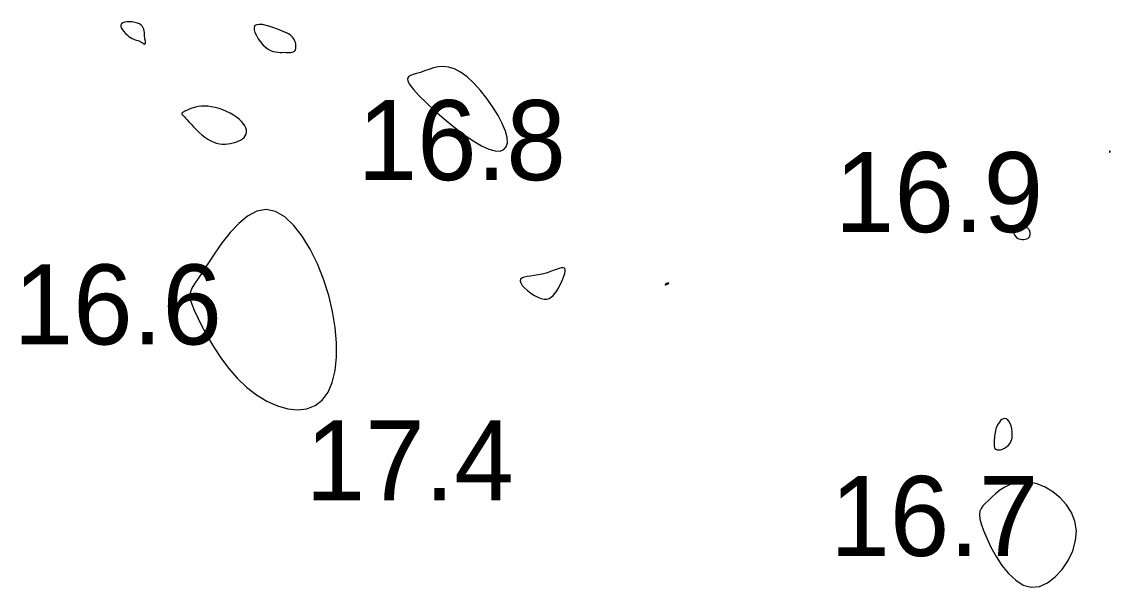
# Model space of a CAD drawing. Extents: x 3040093 to 3056816, y 408076 to 509144.
# Drawn here: x 3045420.5 to 3045488.5, y 433988.6 to 434023.9 of the extents above; entities that cross this region are included whole.
import ezdxf

# ---------------------------------------------------------------- set-up
doc = ezdxf.new("R2010")
doc.units = 0
doc.layers.add('V-CHAN-CONT-EL17', color=7, linetype='Continuous')
doc.layers.add('V-TOPO-SOUN-0610', color=7, linetype='Continuous')

msp = doc.modelspace()

# ---------------------------------------------------------------- linework, layer by layer
at = {"layer": 'V-CHAN-CONT-EL17'}
for points in [[(3045427.309, 434022.925), (3045427.41, 434022.867), (3045427.506, 434022.821), (3045427.596, 434022.784), (3045427.679, 434022.755), (3045427.755, 434022.73), (3045427.824, 434022.708), (3045427.884, 434022.686), (3045427.936, 434022.663), (3045427.981, 434022.638), (3045428.019, 434022.614), (3045428.051, 434022.59), (3045428.079, 434022.568), (3045428.104, 434022.549), (3045428.126, 434022.533), (3045428.146, 434022.522), (3045428.166, 434022.517), (3045428.184, 434022.516), (3045428.201, 434022.521), (3045428.216, 434022.532), (3045428.228, 434022.547), (3045428.238, 434022.567), (3045428.243, 434022.591), (3045428.245, 434022.621), (3045428.242, 434022.654), (3045428.236, 434022.693), (3045428.227, 434022.738), (3045428.217, 434022.788), (3045428.206, 434022.845), (3045428.195, 434022.909), (3045428.186, 434022.98), (3045428.18, 434023.06), (3045428.176, 434023.148), (3045428.171, 434023.242), (3045428.161, 434023.339), (3045428.141, 434023.436), (3045428.107, 434023.531), (3045428.054, 434023.62), (3045427.978, 434023.701), (3045427.874, 434023.771), (3045427.74, 434023.828), (3045427.584, 434023.87), (3045427.416, 434023.897), (3045427.245, 434023.908), (3045427.082, 434023.903), (3045426.936, 434023.88), (3045426.817, 434023.839), (3045426.735, 434023.78), (3045426.697, 434023.703), (3045426.699, 434023.611), (3045426.735, 434023.509), (3045426.799, 434023.4), (3045426.884, 434023.29), (3045426.984, 434023.184), (3045427.092, 434023.085), (3045427.202, 434022.997)], [(3045435.901, 434022.2), (3045436.059, 434022.115), (3045436.213, 434022.058), (3045436.363, 434022.023), (3045436.509, 434022.004), (3045436.648, 434021.997), (3045436.782, 434021.997), (3045436.908, 434021.999), (3045437.026, 434021.997), (3045437.136, 434021.995), (3045437.237, 434021.994), (3045437.328, 434021.997), (3045437.409, 434022.006), (3045437.478, 434022.025), (3045437.536, 434022.056), (3045437.581, 434022.101), (3045437.613, 434022.161), (3045437.633, 434022.236), (3045437.642, 434022.321), (3045437.639, 434022.413), (3045437.627, 434022.509), (3045437.605, 434022.606), (3045437.575, 434022.701), (3045437.536, 434022.789), (3045437.49, 434022.87), (3045437.434, 434022.944), (3045437.364, 434023.014), (3045437.278, 434023.081), (3045437.172, 434023.147), (3045437.043, 434023.215), (3045436.888, 434023.288), (3045436.704, 434023.366), (3045436.491, 434023.451), (3045436.256, 434023.537), (3045436.013, 434023.616), (3045435.773, 434023.682), (3045435.548, 434023.727), (3045435.349, 434023.744), (3045435.189, 434023.725), (3045435.08, 434023.664), (3045435.029, 434023.556), (3045435.032, 434023.408), (3045435.081, 434023.233), (3045435.169, 434023.04), (3045435.287, 434022.841), (3045435.427, 434022.647), (3045435.581, 434022.469), (3045435.742, 434022.317)], [(3045449.703, 434015.94), (3045450.091, 434015.834), (3045450.402, 434015.828), (3045450.633, 434015.915), (3045450.784, 434016.089), (3045450.851, 434016.346), (3045450.833, 434016.678), (3045450.728, 434017.08), (3045450.537, 434017.544), (3045450.272, 434018.05), (3045449.947, 434018.576), (3045449.576, 434019.102), (3045449.175, 434019.605), (3045448.756, 434020.064), (3045448.336, 434020.457), (3045447.927, 434020.763), (3045447.543, 434020.966), (3045447.183, 434021.076), (3045446.845, 434021.112), (3045446.529, 434021.088), (3045446.23, 434021.023), (3045445.948, 434020.932), (3045445.681, 434020.834), (3045445.426, 434020.744), (3045445.184, 434020.675), (3045444.968, 434020.616), (3045444.79, 434020.553), (3045444.666, 434020.472), (3045444.61, 434020.358), (3045444.636, 434020.196), (3045444.759, 434019.972), (3045444.993, 434019.671), (3045445.346, 434019.286), (3045445.8, 434018.834), (3045446.329, 434018.341), (3045446.909, 434017.832), (3045447.515, 434017.334), (3045448.122, 434016.871), (3045448.705, 434016.468), (3045449.239, 434016.151)], [(3045430.523, 434018.118), (3045430.534, 434018.106), (3045430.551, 434018.088), (3045430.578, 434018.061), (3045430.617, 434018.02), (3045430.672, 434017.962), (3045430.744, 434017.883), (3045430.836, 434017.781), (3045430.951, 434017.654), (3045431.086, 434017.506), (3045431.238, 434017.344), (3045431.404, 434017.175), (3045431.579, 434017.006), (3045431.762, 434016.844), (3045431.949, 434016.694), (3045432.137, 434016.564), (3045432.323, 434016.459), (3045432.506, 434016.379), (3045432.687, 434016.321), (3045432.865, 434016.284), (3045433.042, 434016.266), (3045433.216, 434016.264), (3045433.387, 434016.277), (3045433.557, 434016.303), (3045433.724, 434016.339), (3045433.885, 434016.387), (3045434.036, 434016.445), (3045434.175, 434016.513), (3045434.298, 434016.592), (3045434.4, 434016.681), (3045434.48, 434016.78), (3045434.532, 434016.89), (3045434.554, 434017.009), (3045434.546, 434017.136), (3045434.51, 434017.269), (3045434.446, 434017.406), (3045434.355, 434017.545), (3045434.237, 434017.684), (3045434.095, 434017.82), (3045433.929, 434017.953), (3045433.74, 434018.08), (3045433.532, 434018.198), (3045433.31, 434018.307), (3045433.078, 434018.403), (3045432.841, 434018.486), (3045432.602, 434018.553), (3045432.368, 434018.601), (3045432.142, 434018.63), (3045431.927, 434018.638), (3045431.726, 434018.628), (3045431.539, 434018.603), (3045431.368, 434018.567), (3045431.212, 434018.524), (3045431.072, 434018.477), (3045430.951, 434018.429), (3045430.847, 434018.385), (3045430.762, 434018.347), (3045430.694, 434018.315), (3045430.641, 434018.288), (3045430.601, 434018.266), (3045430.571, 434018.247), (3045430.55, 434018.232), (3045430.535, 434018.218), (3045430.525, 434018.206), (3045430.517, 434018.194), (3045430.511, 434018.183), (3045430.508, 434018.172), (3045430.506, 434018.162), (3045430.506, 434018.153), (3045430.508, 434018.143), (3045430.511, 434018.135), (3045430.516, 434018.126)], [(3045488.48, 434015.757), (3045488.486, 434015.754), (3045488.491, 434015.753), (3045488.496, 434015.752), (3045488.502, 434015.753), (3045488.506, 434015.755), (3045488.51, 434015.759), (3045488.514, 434015.764), (3045488.516, 434015.77), (3045488.517, 434015.778), (3045488.516, 434015.786), (3045488.515, 434015.794), (3045488.513, 434015.803), (3045488.511, 434015.81), (3045488.507, 434015.817), (3045488.503, 434015.821), (3045488.499, 434015.824), (3045488.494, 434015.826), (3045488.489, 434015.825), (3045488.484, 434015.824), (3045488.479, 434015.821), (3045488.475, 434015.817), (3045488.471, 434015.812), (3045488.468, 434015.806), (3045488.466, 434015.8), (3045488.464, 434015.794), (3045488.464, 434015.788), (3045488.465, 434015.781), (3045488.466, 434015.775), (3045488.469, 434015.77), (3045488.472, 434015.765), (3045488.476, 434015.76)], [(3045435.178, 434000.588), (3045435.825, 434000.196), (3045436.48, 433999.905), (3045437.127, 433999.723), (3045437.748, 433999.659), (3045438.327, 433999.721), (3045438.847, 433999.918), (3045439.291, 434000.259), (3045439.646, 434000.749), (3045439.91, 434001.372), (3045440.086, 434002.108), (3045440.174, 434002.939), (3045440.176, 434003.844), (3045440.095, 434004.804), (3045439.932, 434005.798), (3045439.689, 434006.809), (3045439.37, 434007.813), (3045438.981, 434008.783), (3045438.535, 434009.689), (3045438.041, 434010.499), (3045437.508, 434011.184), (3045436.948, 434011.713), (3045436.369, 434012.056), (3045435.783, 434012.182), (3045435.198, 434012.075), (3045434.623, 434011.767), (3045434.066, 434011.304), (3045433.534, 434010.734), (3045433.036, 434010.102), (3045432.578, 434009.454), (3045432.17, 434008.837), (3045431.818, 434008.297), (3045431.529, 434007.867), (3045431.304, 434007.532), (3045431.143, 434007.262), (3045431.046, 434007.029), (3045431.012, 434006.803), (3045431.041, 434006.556), (3045431.133, 434006.26), (3045431.288, 434005.884), (3045431.505, 434005.41), (3045431.782, 434004.851), (3045432.116, 434004.233), (3045432.505, 434003.578), (3045432.946, 434002.91), (3045433.437, 434002.254), (3045433.974, 434001.633), (3045434.557, 434001.07)], [(3045482.714, 434010.39), (3045482.805, 434010.347), (3045482.903, 434010.317), (3045483.005, 434010.302), (3045483.106, 434010.3), (3045483.202, 434010.311), (3045483.289, 434010.334), (3045483.363, 434010.369), (3045483.422, 434010.416), (3045483.465, 434010.471), (3045483.494, 434010.533), (3045483.511, 434010.598), (3045483.517, 434010.665), (3045483.513, 434010.731), (3045483.502, 434010.794), (3045483.485, 434010.85), (3045483.462, 434010.899), (3045483.435, 434010.94), (3045483.401, 434010.975), (3045483.362, 434011.005), (3045483.316, 434011.031), (3045483.264, 434011.055), (3045483.204, 434011.077), (3045483.137, 434011.1), (3045483.061, 434011.123), (3045482.981, 434011.144), (3045482.898, 434011.162), (3045482.815, 434011.172), (3045482.735, 434011.174), (3045482.661, 434011.164), (3045482.596, 434011.14), (3045482.542, 434011.1), (3045482.502, 434011.04), (3045482.477, 434010.966), (3045482.466, 434010.881), (3045482.469, 434010.79), (3045482.488, 434010.697), (3045482.522, 434010.606), (3045482.571, 434010.522), (3045482.635, 434010.449)], [(3045451.683, 434007.584), (3045451.783, 434007.434), (3045451.93, 434007.27), (3045452.113, 434007.104), (3045452.321, 434006.945), (3045452.54, 434006.803), (3045452.759, 434006.687), (3045452.966, 434006.607), (3045453.152, 434006.571), (3045453.318, 434006.577), (3045453.465, 434006.621), (3045453.598, 434006.698), (3045453.719, 434006.805), (3045453.83, 434006.938), (3045453.935, 434007.093), (3045454.037, 434007.266), (3045454.137, 434007.451), (3045454.231, 434007.643), (3045454.316, 434007.833), (3045454.385, 434008.015), (3045454.435, 434008.181), (3045454.46, 434008.323), (3045454.455, 434008.434), (3045454.415, 434008.506), (3045454.338, 434008.536), (3045454.226, 434008.527), (3045454.082, 434008.489), (3045453.91, 434008.429), (3045453.715, 434008.356), (3045453.501, 434008.276), (3045453.27, 434008.199), (3045453.028, 434008.133), (3045452.778, 434008.082), (3045452.531, 434008.044), (3045452.295, 434008.011), (3045452.081, 434007.977), (3045451.899, 434007.937), (3045451.759, 434007.884), (3045451.67, 434007.811), (3045451.643, 434007.712)], [(3045460.899, 434007.542), (3045460.91, 434007.546), (3045460.921, 434007.549), (3045460.93, 434007.553), (3045460.937, 434007.556), (3045460.941, 434007.559), (3045460.94, 434007.561), (3045460.936, 434007.564), (3045460.926, 434007.566), (3045460.912, 434007.567), (3045460.894, 434007.567), (3045460.874, 434007.567), (3045460.853, 434007.564), (3045460.83, 434007.561), (3045460.808, 434007.555), (3045460.787, 434007.547), (3045460.768, 434007.536), (3045460.751, 434007.524), (3045460.736, 434007.51), (3045460.724, 434007.497), (3045460.714, 434007.484), (3045460.708, 434007.472), (3045460.705, 434007.463), (3045460.705, 434007.456), (3045460.709, 434007.453), (3045460.716, 434007.453), (3045460.725, 434007.456), (3045460.737, 434007.461), (3045460.75, 434007.468), (3045460.764, 434007.475), (3045460.778, 434007.483), (3045460.791, 434007.491), (3045460.805, 434007.499), (3045460.817, 434007.505), (3045460.829, 434007.512), (3045460.841, 434007.518), (3045460.852, 434007.523), (3045460.863, 434007.528), (3045460.875, 434007.533), (3045460.887, 434007.537)], [(3045481.265, 433997.685), (3045481.258, 433997.579), (3045481.256, 433997.479), (3045481.263, 433997.388), (3045481.282, 433997.307), (3045481.316, 433997.241), (3045481.369, 433997.191), (3045481.443, 433997.16), (3045481.541, 433997.15), (3045481.657, 433997.162), (3045481.783, 433997.196), (3045481.914, 433997.253), (3045482.041, 433997.332), (3045482.159, 433997.435), (3045482.259, 433997.561), (3045482.335, 433997.711), (3045482.381, 433997.884), (3045482.399, 433998.072), (3045482.393, 433998.268), (3045482.366, 433998.461), (3045482.32, 433998.644), (3045482.259, 433998.807), (3045482.187, 433998.942), (3045482.107, 433999.041), (3045482.021, 433999.097), (3045481.932, 433999.113), (3045481.843, 433999.094), (3045481.755, 433999.047), (3045481.671, 433998.977), (3045481.593, 433998.888), (3045481.522, 433998.788), (3045481.462, 433998.681), (3045481.413, 433998.571), (3045481.375, 433998.461), (3045481.345, 433998.35), (3045481.323, 433998.239), (3045481.307, 433998.127), (3045481.294, 433998.016), (3045481.284, 433997.905), (3045481.275, 433997.794)], [(3045484.093, 433988.62), (3045484.6, 433988.844), (3045485.083, 433989.208), (3045485.521, 433989.684), (3045485.893, 433990.24), (3045486.178, 433990.848), (3045486.356, 433991.478), (3045486.405, 433992.1), (3045486.314, 433992.688), (3045486.098, 433993.232), (3045485.779, 433993.723), (3045485.383, 433994.155), (3045484.931, 433994.52), (3045484.448, 433994.811), (3045483.956, 433995.019), (3045483.48, 433995.138), (3045483.038, 433995.165), (3045482.634, 433995.111), (3045482.265, 433994.992), (3045481.93, 433994.824), (3045481.629, 433994.624), (3045481.358, 433994.408), (3045481.117, 433994.191), (3045480.904, 433993.989), (3045480.72, 433993.813), (3045480.567, 433993.653), (3045480.451, 433993.493), (3045480.376, 433993.315), (3045480.348, 433993.105), (3045480.372, 433992.846), (3045480.452, 433992.522), (3045480.594, 433992.116), (3045480.8, 433991.623), (3045481.066, 433991.07), (3045481.387, 433990.493), (3045481.755, 433989.931), (3045482.165, 433989.42), (3045482.61, 433988.998), (3045483.084, 433988.7), (3045483.581, 433988.566)]]:
    msp.add_lwpolyline(points, close=True, dxfattribs=at)

# ---------------------------------------------------------------- texts
at = {"layer": 'V-TOPO-SOUN-0610'}
for s, p in [('16.8 ', (3045441.493, 434014.01)), ('16.9 ', (3045471.313, 434010.76)), ('16.6 ', (3045420.003, 434003.74)), ('17.4 ', (3045438.243, 433993.99)), ('16.7 ', (3045471.023, 433990.52))]:
    msp.add_text(s, height=5, dxfattribs=at).set_placement(p)

doc.saveas('drawing.dxf')
